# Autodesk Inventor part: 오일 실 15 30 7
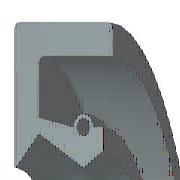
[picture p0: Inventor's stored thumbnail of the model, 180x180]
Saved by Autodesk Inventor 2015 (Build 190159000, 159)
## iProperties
IsCustomPart: 1
Created: 2012-02
Part Number: 오일 실 15 30 7
Material: 고무
Description: 오일-실
Document SubType Name: Modeling
Standard: KS B 2804
Designer: mduedu
Standards Organization: KS
Language: ko-KR
Size Designation: D - 15 30 7
Categories: <MemberInstance><Categories><Category DisplayName="샤프트 부품" InternalName="7f7aeb1f-a693-4053-b835-cee3144e0d98" Mnemonic="SHFT"><Category DisplayName="실링" Intern
Density: 0.93 g/cm^3
Appearance: 고무 - 검은색 - 버전 1.1
Author: mduedu
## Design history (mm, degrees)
revolve "본체" stored, may be unused: angle "d17" = 90 deg
revolve "스프링1" stored, may be unused: angle "d18" = 90 deg
body "Solid1"
sketch "스케치1"
  geometry: L1 (0, 15)-(7, 15); L2 (7, 13.25)-(1.75, 13.25); L3 (1.75, 9.25)-(4.9, 7.5); L4 (4.9, 7.5)-(0, 7.5); L5 (0, 0)-(9.586, 0) reference; L6 (4.9, 7.5)-(6.3, 8.375); L7 (0, 18)-(0, -3) reference; L8 (-1.941, 0)-(11.507, 0) reference; L9 (4.2, 9.6)-(1.75, 10.09); L10 (1.75, 10.09)-(1.75, 13.25); L11 (0, 15)-(0, 7.588); L12 (4.9, 7.5)-(0, 7.5); L13 (1.75, 9.25)-(0.152, 7.528); L14 (7, 15)-(7, 13.25); L15 (5.6, 9.6)-(6.3, 9.6); L16 (6.3, 9.6)-(6.3, 8.375); C1 r 0.455 at (4.9, 9.6); A1 r 0.7 centre (4.9, 9.6) between (5.6, 9.6) and (4.2, 9.6); A2 r 0.088 centre (0.088, 7.588) between (0, 7.588) and (0.152, 7.528); 1 further point
  constraints: 28 end point, 5 horizontal alignment, 5 point on line, 4 point on circle, 4 vertical alignment, 3 centre point, 3 tangent, 2 collinear, 2 horizontal, 2 perpendicular, 1 coincident, 1 parallel
  dimensions: "d0" = 30 diameter of L1 L5 (= SD2); "d1" = 1.75 distance of L1.end L2.start (= SD); "d2" = 0.91 diameter of C1 (= SPDI); "d3" = 1.4 diameter of A1 (= SPDA); "d4" = 15 diameter of L3.end L5 (= NND); "d5" = 18.5 diameter of L3.start L5 (= TKDM); "d7" = 20.18 diameter of L9.end L5 (= TKDM + 0.24 x SWDT); "d8" = 1.75 distance between parallel lines of L11 L10 (= SD); "d9" = 4.9 distance from line of L11 C1.centre (= SPDST); "d10" = 19.2 diameter of C1.centre L5 (= HLDM); "d11" = 0.0875 radius of A2 (= 0.25 x LAB); "d12" = 6.3 distance between parallel lines of L11 L16 (= SDI); "d13" = 16.75 diameter of L6.end L5 (= ABDM); "d14" = 7 distance from line of L11 L1.end (= SWDT)
fillet "모깎기1" dims "d6" = 0.3 (= RR)
other parameters: "SD2" = 30 [user parameter; used in 1 equation term], "SWDT" = 7 [user parameter; used in 2 equation terms], "RR" = 0.3 [user parameter; used in 1 equation term], "SD" = 1.75 [user parameter; used in 2 equation terms], "NND" = 15 [user parameter; used in 1 equation term], "SPDA" = 1.4 [user parameter; used in 1 equation term], "SPDI" = 0.91 [user parameter; used in 1 equation term], "TKDM" = 18.5 [user parameter; used in 2 equation terms], "HLDM" = 19.2 [user parameter; used in 1 equation term], "ABDM" = 16.75 [user parameter; used in 1 equation term], "SDI" = 6.3 [user parameter; used in 1 equation term], "SPDST" = 4.9 [user parameter; used in 1 equation term], "LAB" = 0.35 [user parameter; used in 1 equation term], "d15" = 0, "d16" = 0, "d19" = 0
